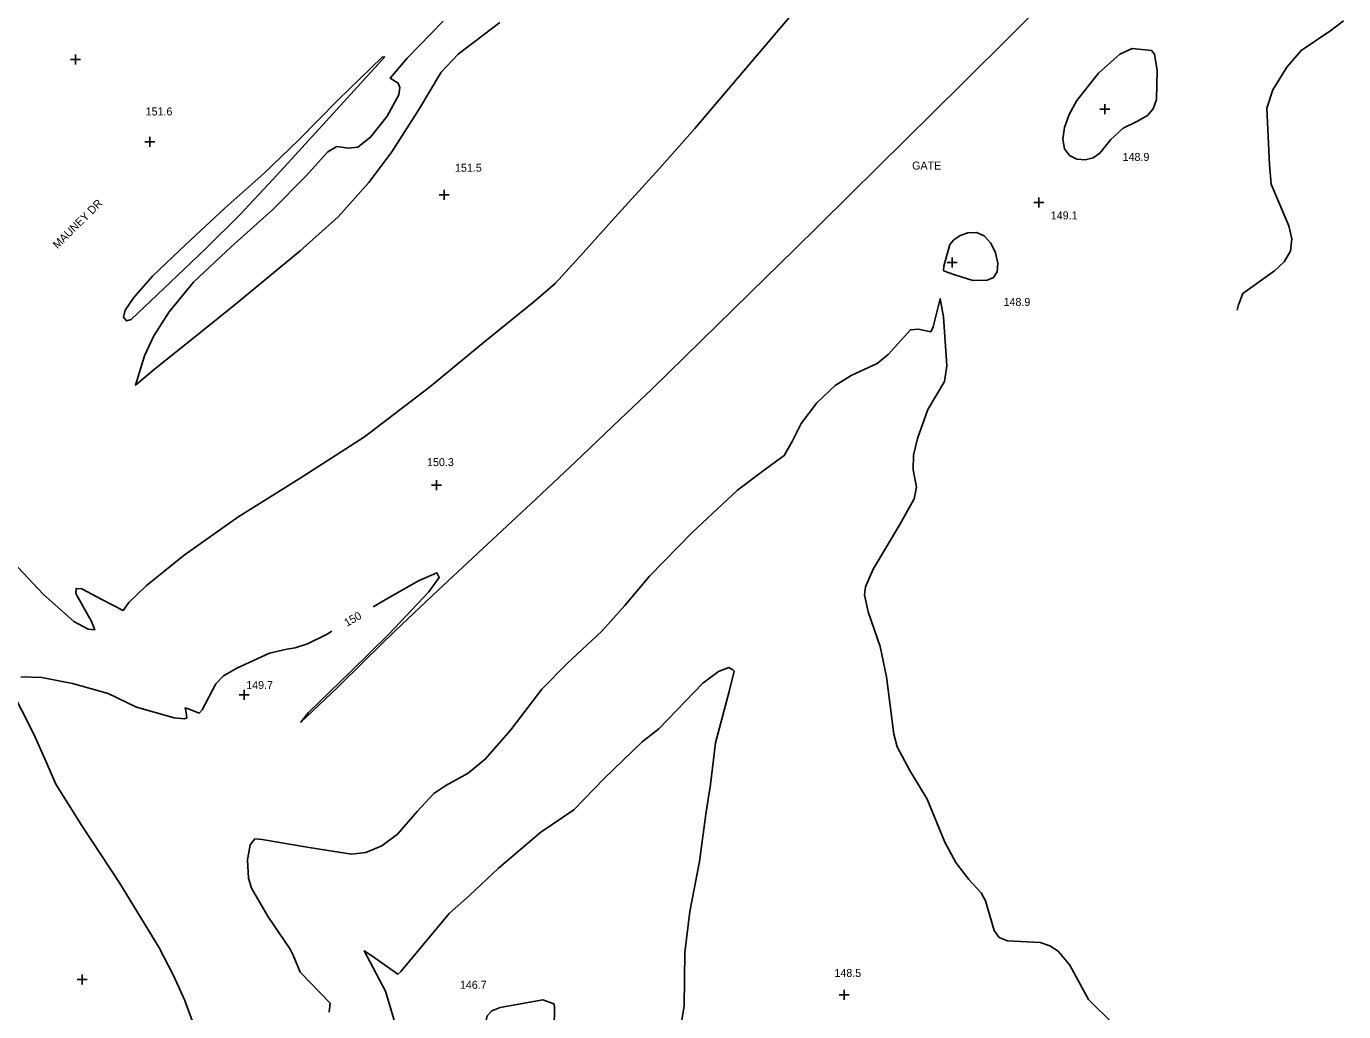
# Model space of a CAD drawing. Extents: x 1467615 to 2003689, y 770235 to 1108726.
# Drawn here: x 2001995.6 to 2002324.8, y 771945.8 to 772192.1 of the extents above; entities that cross this region are included whole.
import ezdxf

# ---------------------------------------------------------------- set-up
doc = ezdxf.new("R2010")
doc.units = 0
for name, color, linetype in [('RD_DTM_Major1', 7, 'Continuous'), ('RD_DTM_Major1_Lbl', 7, 'Continuous'), ('RD_DTM_Minor1', 7, 'Continuous'), ('RD_DTM_Spot_Elev', 7, 'Continuous'), ('RD_TX_Misc1', 7, 'Continuous')]:
    doc.layers.add(name, color=color, linetype=linetype)

msp = doc.modelspace()

# ---------------------------------------------------------------- linework, layer by layer
at = {"layer": 'RD_DTM_Major1'}
for points in [[(2002082.24, 772046.95), (2002086.22, 772049.29), (2002093.55, 772053.46), (2002098.18, 772055.49), (2002098.79, 772054.35), (2002096.14, 772050.71), (2002086.14, 772040.14), (2002076.6, 772030.76), (2002066.1, 772020.56), (2002064.2, 772018.12), (2002073.22, 772026.71), (2002080.08, 772033.51), (2002087.78, 772041), (2002098.49, 772051.14), (2002110.84, 772062.68), (2002122.97, 772073.97), (2002132.86, 772083.22), (2002143.94, 772093.81), (2002151.97, 772101.44), (2002164.14, 772113.36), (2002176.45, 772125.46), (2002187.63, 772136.38), (2002193.48, 772142.16), (2002201.5, 772150.06), (2002215.34, 772163.72), (2002229.55, 772177.77), (2002241.97, 772190.13), (2002250.97, 772199.22)], [(2002324.83, 772193.46), (2002321.64, 772191.02), (2002314.19, 772186.08), (2002310.66, 772181.93), (2002307.12, 772176.22), (2002305.61, 772171.64), (2002306.31, 772157.49), (2002306.71, 772152.67), (2002308.54, 772148.3), (2002311.14, 772142.25), (2002311.84, 772138.97), (2002311.53, 772135.88), (2002309.95, 772133.21), (2002307.53, 772131), (2002299.61, 772125.33), (2002298.58, 772122.51), (2002298.22, 772121.12)], [(2001994.19, 772029.5), (2001999.46, 772029.28), (2002007.11, 772027.83), (2002015.98, 772025.34), (2002023.11, 772021.88), (2002032.5, 772019.27), (2002035.1, 772018.95), (2002035.65, 772019.23), (2002035.47, 772020.61), (2002035.25, 772021.72), (2002036.49, 772021.35), (2002038.76, 772020.44), (2002039.5, 772021.2), (2002042.96, 772027.72), (2002044.87, 772029.73), (2002048.14, 772031.67), (2002056.33, 772035.42), (2002060.69, 772036.41), (2002062.74, 772036.7), (2002065.8, 772037.73), (2002070.74, 772040.18), (2002071.9, 772040.86)], [(2001987.63, 771939.65), (2002000.25, 771932.86), (2002011.44, 771927), (2002025.57, 771919.59), (2002037.24, 771913.92), (2002043.47, 771911.47), (2002045.02, 771911.3), (2002046, 771911.81), (2002046.28, 771913.14), (2002045.48, 771917.02), (2002042.37, 771926.56), (2002039.02, 771938.06), (2002035.2, 771948.56), (2002032.37, 771954.82), (2002028.66, 771961.92), (2002018.86, 771977.98), (2002009.54, 771992.14), (2002002.91, 772002.64), (2002000.53, 772008.23), (2001997.44, 772015.16), (2001991.47, 772026.97)]]:
    msp.add_lwpolyline(points, dxfattribs=at)
at = {"layer": 'RD_DTM_Minor1'}
for points in [[(2001990.9, 772059.54), (2001999.73, 772050.15), (2002007.43, 772043.33), (2002010.99, 772041.39), (2002012.65, 772041.22), (2002011.81, 772043.28), (2002007.97, 772050.29), (2002007.98, 772051.58), (2002009.42, 772051.48), (2002014.56, 772048.77), (2002019.79, 772046.09), (2002021.15, 772048.08), (2002025.49, 772052.22), (2002035.03, 772059.93), (2002048.43, 772069.44), (2002063.78, 772078.94), (2002080.12, 772089.49), (2002096.37, 772101.92), (2002110.13, 772113.33), (2002122.41, 772123.22), (2002127.72, 772127.79), (2002134.72, 772135.51), (2002142.67, 772144.31), (2002153.76, 772156.44), (2002162.68, 772166.54), (2002168.24, 772173.17), (2002178.23, 772184.86), (2002190.56, 772199.51)], [(2002099.77, 772193.37), (2002090.79, 772184.17), (2002086.54, 772179.12), (2002088.53, 772177.9), (2002088.95, 772176.78), (2002088.7, 772175.01), (2002085.78, 772169.61), (2002081.62, 772164.36), (2002078.41, 772161.93), (2002076.12, 772161.66), (2002073.21, 772162.08), (2002070.91, 772160.76), (2002065.34, 772154.55), (2002057.13, 772146.25), (2002046.8, 772136.98), (2002037.34, 772128.16), (2002031.23, 772120.71), (2002027.4, 772114.74), (2002025.13, 772109.7), (2002022.82, 772102.42), (2002027.53, 772106.31), (2002039.3, 772115.76), (2002047.78, 772122.58), (2002064.04, 772135.97), (2002073.47, 772144.48), (2002081.14, 772153.02), (2002086.89, 772160.75), (2002093.83, 772171.55), (2002099.29, 772180.63), (2002103.51, 772185.18), (2002113.91, 772193.08)], [(2002277.52, 772185.1), (2002278.18, 772181.02), (2002278.03, 772173.81), (2002277.19, 772171.5), (2002275.79, 772169.83), (2002273.17, 772168.31), (2002269.73, 772166.61), (2002266.64, 772163.77), (2002263.87, 772160.42), (2002262.2, 772159.24), (2002260.21, 772158.72), (2002258.12, 772158.92), (2002256.29, 772159.84), (2002255.02, 772161.49), (2002254.6, 772163.85), (2002255.02, 772166.77), (2002256.22, 772170.07), (2002258.15, 772173.57), (2002263.57, 772180.36), (2002268.87, 772185.14), (2002271.99, 772186.57), (2002276.8, 772186.08), (2002277.52, 772185.1)], [(2002057.18, 772153.84), (2002048.96, 772145), (2002040.33, 772136.44), (2002031.56, 772128.13), (2002021.76, 772118.85), (2002020.59, 772118.52), (2002019.84, 772119.38), (2002020.25, 772121.16), (2002022.41, 772124.35), (2002027.13, 772129.65), (2002035.55, 772137.63), (2002045.15, 772146.61), (2002054.94, 772155.35), (2002063.57, 772163.65), (2002073.51, 772173.7), (2002084.48, 772184.43), (2002085.15, 772184.47), (2002079.23, 772177.95), (2002070.52, 772168.35), (2002060.07, 772156.97), (2002057.18, 772153.84)], [(2002227.61, 772129.97), (2002224.84, 772131.01), (2002224.86, 772132.15), (2002226.42, 772137.54), (2002227.42, 772138.74), (2002228.98, 772139.8), (2002230.93, 772140.49), (2002233.02, 772140.55), (2002235, 772139.73), (2002236.66, 772137.91), (2002237.84, 772135.46), (2002238.41, 772132.89), (2002238.24, 772130.71), (2002237.27, 772129.3), (2002235.73, 772128.61), (2002232.18, 772128.57), (2002227.61, 772129.97)], [(2002071.28, 771945.62), (2002071.48, 771947.95), (2002063.98, 771955.68), (2002062.27, 771959.93), (2002061.51, 771961.37), (2002056.02, 771969.48), (2002051.8, 771976.66), (2002051.09, 771979.12), (2002050.8, 771983.75), (2002051.51, 771987.46), (2002052.71, 771988.98), (2002054.54, 771988.85), (2002066.27, 771986.85), (2002076.86, 771985.12), (2002080.44, 771985.59), (2002084.43, 771987.25), (2002088.33, 771990.13), (2002093.27, 771995.82), (2002097.44, 772000.32), (2002100.4, 772002.32), (2002105.98, 772005.37), (2002110.36, 772008.96), (2002116.7, 772016.26), (2002124.44, 772026.37), (2002130.86, 772032.93), (2002139.44, 772040.92), (2002145.19, 772047.33), (2002151.32, 772054.68), (2002161.98, 772065.58), (2002173.33, 772076.16), (2002179.39, 772080.74), (2002185.02, 772084.79), (2002186.97, 772088.28), (2002189.2, 772092.82), (2002193.12, 772097.96), (2002197.72, 772102.32), (2002201.74, 772104.8), (2002208.23, 772107.78), (2002210.99, 772110.04), (2002216.53, 772116.24), (2002218.57, 772116.36), (2002221.62, 772115.74), (2002222.26, 772116.95), (2002224.01, 772123.98), (2002224.81, 772119.47), (2002225.61, 772107.19), (2002225.04, 772103.29), (2002220.91, 772096.31), (2002218.31, 772089.1), (2002217.28, 772084.93), (2002217.25, 772081.25), (2002218.07, 772076.86), (2002217.44, 772073.98), (2002213.89, 772067.55), (2002207.19, 772056.39), (2002205.32, 772052.01), (2002205.06, 772049.98), (2002206.02, 772045.75), (2002208.96, 772037.04), (2002210.58, 772029.45), (2002212.37, 772015.17), (2002213.26, 772012), (2002216.36, 772006.04), (2002220.71, 771998.88), (2002225.16, 771988.19), (2002227.9, 771983.09), (2002231.17, 771978.8), (2002234.2, 771975.45), (2002235.31, 771973.47), (2002237.44, 771966.05), (2002238.76, 771964.32), (2002240.82, 771963.51), (2002248.99, 771963.08), (2002251.42, 771962.26), (2002253.46, 771960.94), (2002256.38, 771957.44), (2002261.08, 771948.84), (2002267.13, 771942.85)], [(2002088.4, 771940.55), (2002085.33, 771950.93), (2002080.01, 771961), (2002082.21, 771959.61), (2002088.43, 771955.14), (2002089.16, 771955.84), (2002096.74, 771964.91), (2002101.26, 771970.34), (2002106.35, 771974.83), (2002113.57, 771981.63), (2002124.13, 771990.67), (2002132.42, 771996.23), (2002139.95, 772004.11), (2002149.45, 772013.23), (2002153.65, 772016.5), (2002164.68, 772027.89), (2002168.59, 772030.82), (2002171.19, 772031.79), (2002172.12, 772031.2), (2002172.46, 772030.87), (2002171.22, 772025.83), (2002167.85, 772012.97), (2002166.59, 772002.57), (2002165.37, 771995.19), (2002163.85, 771983.33), (2002161.4, 771970.81), (2002160.15, 771960.57), (2002160, 771947.13), (2002158.39, 771937.77)], [(2002127.36, 771928.38), (2002127.06, 771918.32), (2002126.24, 771917.78), (2002124.88, 771917.8), (2002121.51, 771919.21), (2002119.15, 771921.59), (2002117.41, 771925.28), (2002115.23, 771927.14), (2002111.39, 771930.11), (2002109.03, 771933.58), (2002108.78, 771935.95), (2002110.77, 771944.77), (2002111.88, 771946.02), (2002113.99, 771946.82), (2002124.62, 771948.74), (2002127.44, 771947.76), (2002127.54, 771946.98), (2002127.43, 771936.19), (2002127.36, 771928.38)]]:
    msp.add_lwpolyline(points, dxfattribs=at)
at = {"layer": 'RD_DTM_Spot_Elev'}
for p, q in [((2002006.59, 772183.8), (2002009.09, 772183.8)), ((2002007.84, 772182.55), (2002007.84, 772185.05)), ((2002263.87, 772171.38), (2002266.37, 772171.38)), ((2002265.12, 772170.13), (2002265.12, 772172.63)), ((2002025.2, 772163.22), (2002027.7, 772163.22)), ((2002026.45, 772161.97), (2002026.45, 772164.47)), ((2002098.75, 772150), (2002101.25, 772150)), ((2002100, 772148.75), (2002100, 772151.25)), ((2002247.35, 772148.09), (2002249.85, 772148.09)), ((2002248.6, 772146.84), (2002248.6, 772149.34)), ((2002226.99, 772131.84), (2002226.99, 772134.34)), ((2002225.74, 772133.09), (2002228.24, 772133.09)), ((2002098.1, 772076.18), (2002098.1, 772078.68)), ((2002096.85, 772077.43), (2002099.35, 772077.43)), ((2002048.75, 772025), (2002051.25, 772025)), ((2002050, 772023.75), (2002050, 772026.25)), ((2002008.23, 771953.86), (2002010.73, 771953.86)), ((2002009.48, 771952.61), (2002009.48, 771955.11)), ((2002198.75, 771950), (2002201.25, 771950)), ((2002200, 771948.75), (2002200, 771951.25))]:
    msp.add_line(p, q, dxfattribs=at)

# ---------------------------------------------------------------- texts
at = {"layer": 'RD_DTM_Major1_Lbl'}
msp.add_text('150', height=2, rotation=30.4816, dxfattribs=at).set_placement((2002075.71, 772041.95))
at = {"layer": 'RD_DTM_Spot_Elev'}
for s, p in [('151.6', (2002025.38, 772169.82)), ('148.9', (2002269.58, 772158.45)), ('151.5', (2002102.7, 772155.75)), ('149.1', (2002251.63, 772143.84)), ('148.9', (2002239.82, 772122.2)), ('150.3', (2002095.72, 772082.16)), ('149.7', (2002050.52, 772026.43)), ('148.5', (2002197.55, 771954.46)), ('146.7', (2002103.93, 771951.5))]:
    msp.add_text(s, height=2, dxfattribs=at).set_placement(p)
at = {"layer": 'RD_TX_Misc1'}
msp.add_text('GATE', height=2, dxfattribs=at).set_placement((2002216.97, 772156.29))
msp.add_text('MAUNEY DR', height=2, rotation=44.7454, dxfattribs=at).set_placement((2002003.36, 772136.38))

doc.saveas('drawing.dxf')
